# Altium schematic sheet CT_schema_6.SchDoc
size 406 x 311 mm
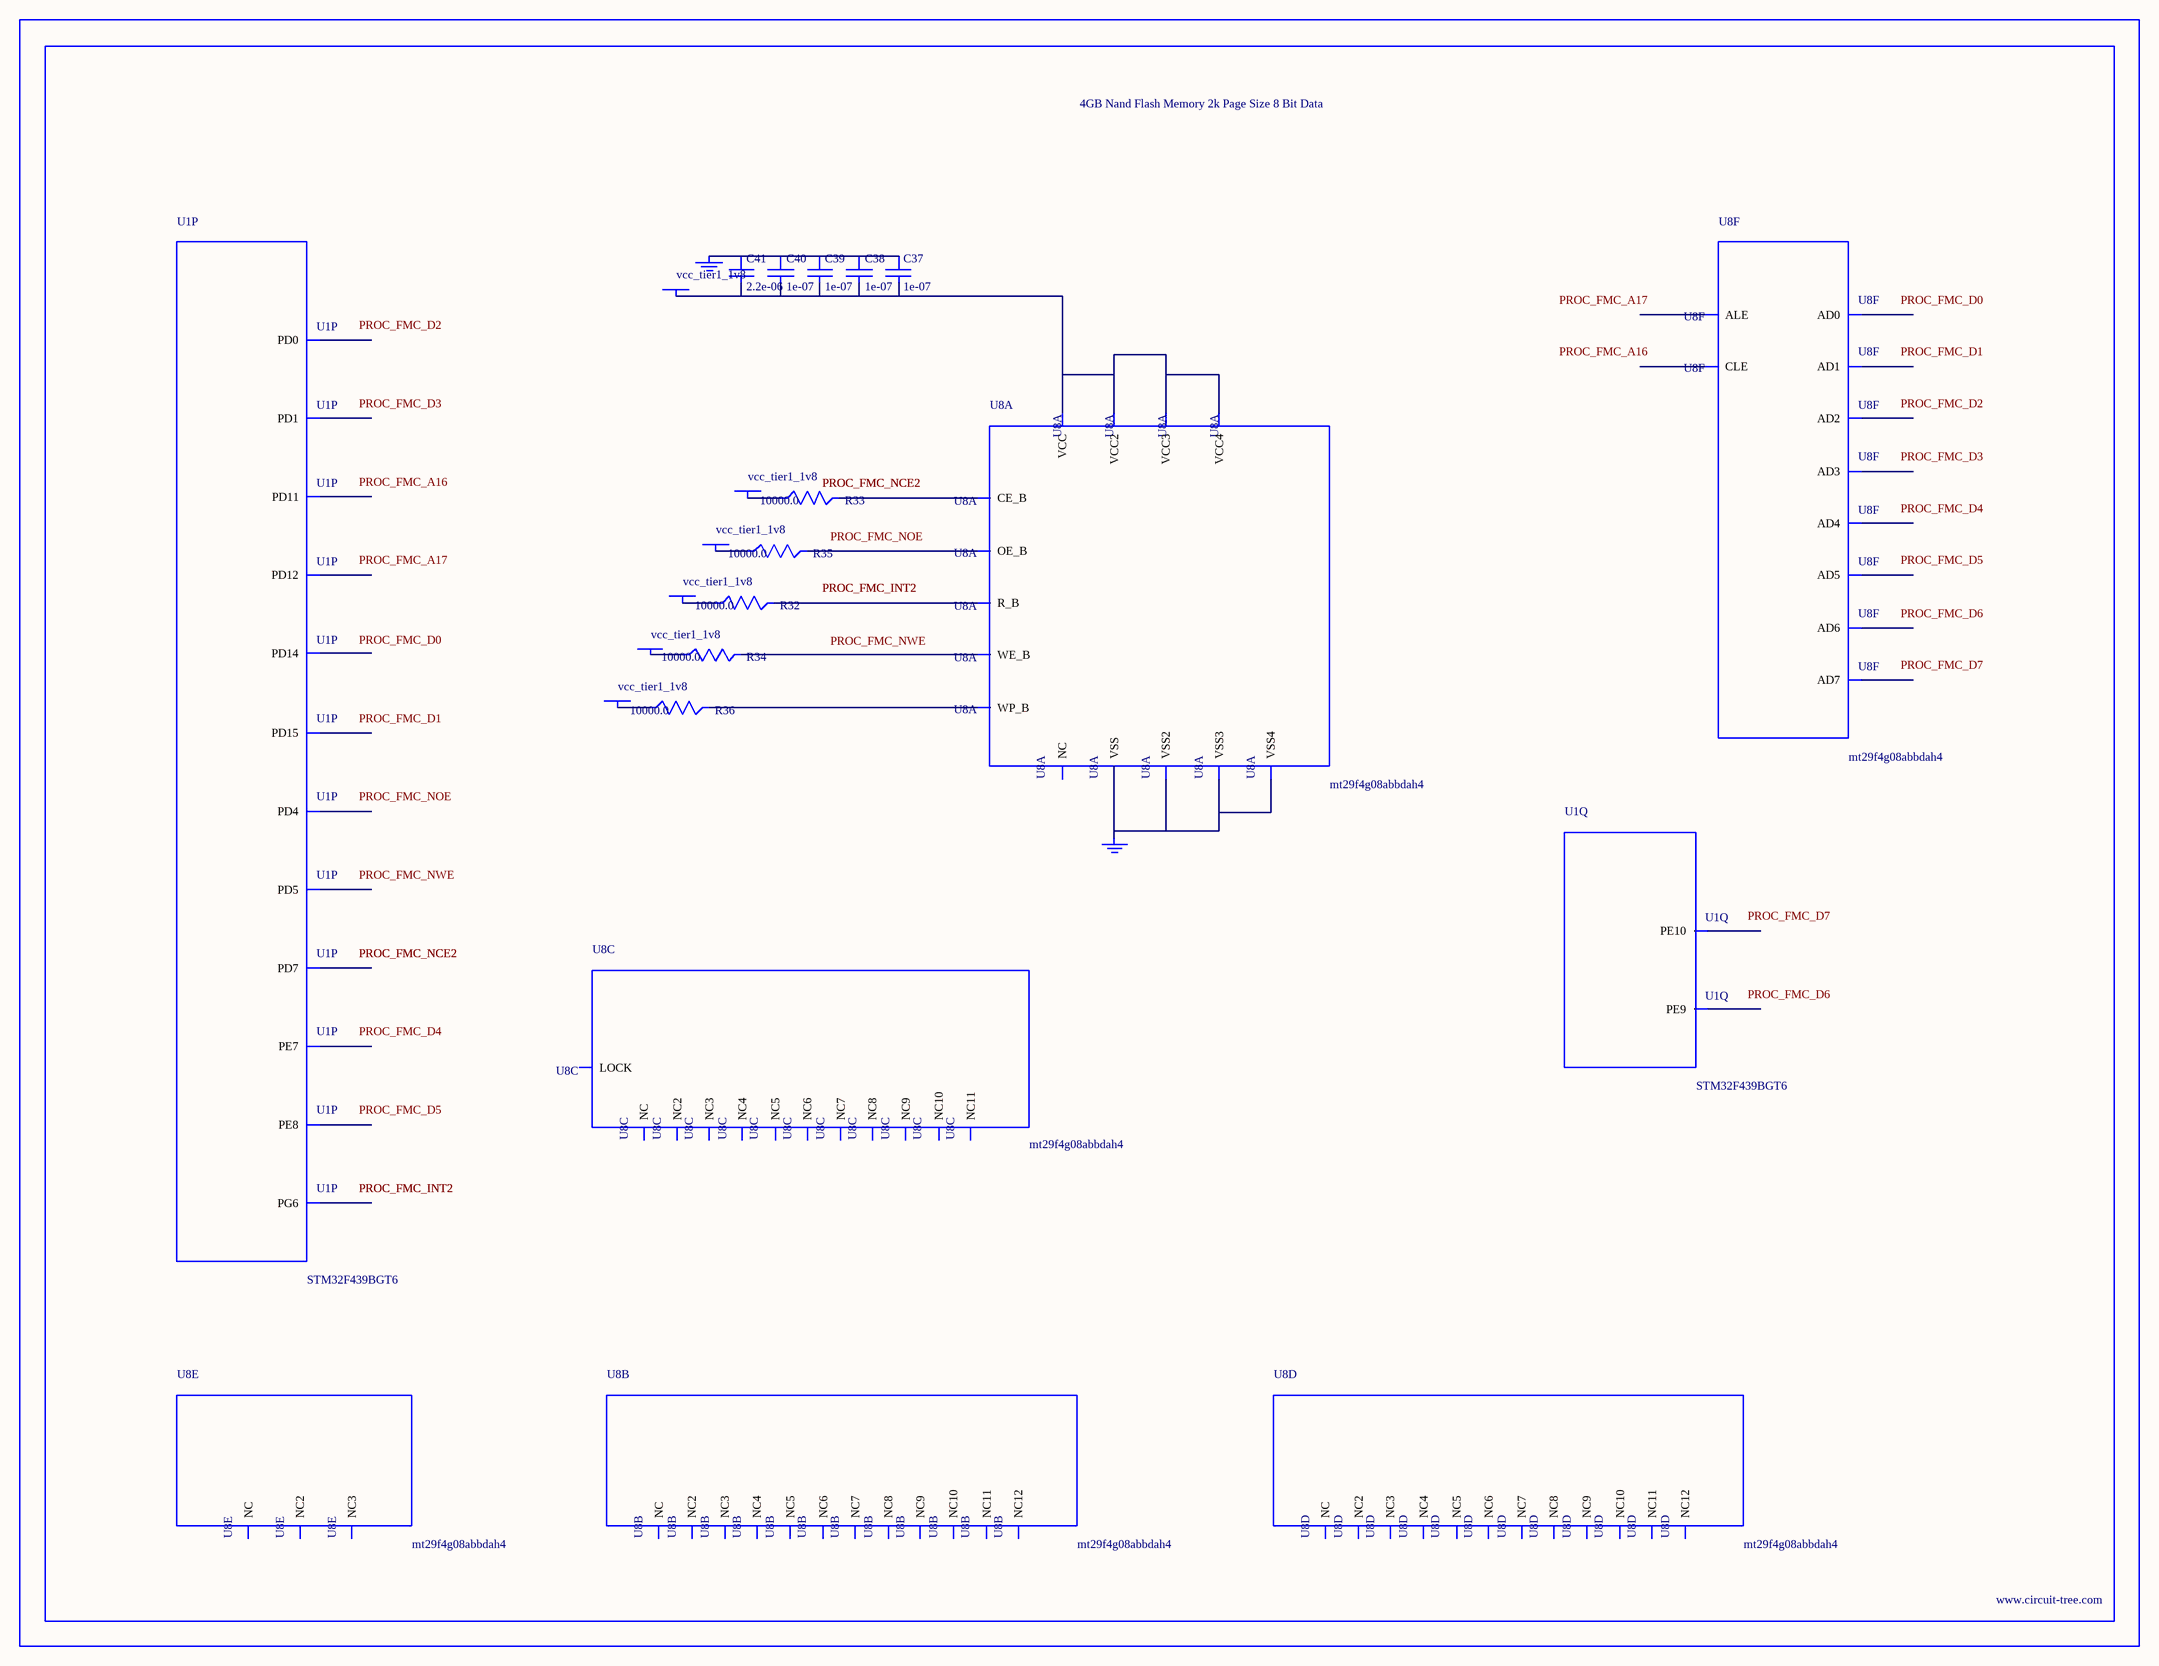
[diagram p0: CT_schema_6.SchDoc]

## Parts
BORDER5  (no value)
C37  1e-07  [C0402]
C38  1e-07  [C0402]
C39  1e-07  [C0402]
C40  1e-07  [C0402]
C41  2.2e-06  [C0603]
GND_INSTANCE_5_0  (no value)
GND_INSTANCE_5_1  (no value)
POWER_INSTANCE_5_0  vcc_tier1_1v8
POWER_INSTANCE_5_1  vcc_tier1_1v8
POWER_INSTANCE_5_2  vcc_tier1_1v8
POWER_INSTANCE_5_3  vcc_tier1_1v8
POWER_INSTANCE_5_4  vcc_tier1_1v8
POWER_INSTANCE_5_5  vcc_tier1_1v8
R32  10000.0  [R0603]
R33  10000.0  [R0603]
R34  10000.0  [R0603]
R35  10000.0  [R0603]
R36  10000.0  [R0603]
U1  STM32F439BGT6  [LQFP208]  (parts P,Q of 18)
U8  mt29f4g08abbdah4  [VFBGA-63]  (parts A,B,C,D,E,F of 6)

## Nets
NetC37_1: C37.1 C38.1 C39.1 C40.1 C41.1 GND_INSTANCE_5_0.0(GND)
NetC37_2: C37.2 C38.2 C39.2 C40.2 C41.2 POWER_INSTANCE_5_0.0(PWR) U8.D3(VCC) U8.G4(VCC2) U8.H8(VCC3) U8.J6(VCC4)
NetGND_INSTANCE_5_1_0: GND_INSTANCE_5_1.0(GND) U8.C5(VSS) U8.F7(VSS2) U8.K3(VSS3) U8.K8(VSS4)
NetPOWER_INSTANCE_5_1_0: POWER_INSTANCE_5_1.0(PWR) R32.1
NetPOWER_INSTANCE_5_2_0: POWER_INSTANCE_5_2.0(PWR) R33.1
NetPOWER_INSTANCE_5_3_0: POWER_INSTANCE_5_3.0(PWR) R34.1
NetPOWER_INSTANCE_5_4_0: POWER_INSTANCE_5_4.0(PWR) R35.1
NetPOWER_INSTANCE_5_5_0: POWER_INSTANCE_5_5.0(PWR) R36.1
NetR32_2: R32.2 U8.C8(R_B)
NetR33_2: R33.2 U8.C6(CE_B)
NetR34_2: R34.2 U8.C7(WE_B)
NetR35_2: R35.2 U8.D4(OE_B)
NetR36_2: R36.2 U8.C3(WP_B)

Not connected (* = marked no-connect by the designer): U1 79(PE7) 80(PE8) 81(PE9) 84(PE10) 111(PD11) 112(PD12) 116(PD14) 117(PD15) 133(PG6) 164(PD0) 165(PD1) 168(PD4) 169(PD5) 173(PD7); U8 A1(NC) A2(NC3) A9(NC4) A10(NC2) B1(NC5) B9(NC7) B10(NC6) C4(ALE) D5(CLE) D6(NC8) D7(NC9) D8(NC10) E3(NC11) E4(NC12) E5(NC) E6(NC2) E7(NC3) E8(NC4) F3(NC5) F4(NC6) F5(NC7) F6(NC8) F8(NC9) G3(NC) G5(LOCK) G6(NC10) G7(NC11) G8(NC) H3(NC2) H4(AD0) H5(NC3) H6(NC4) H7(NC5) J3(NC6) J4(AD1) J5(NC7) J7(AD5) J8(AD7) K4(AD2) K5(AD3) K6(AD4) K7(AD6) L1(NC8) L2(NC10) L9(NC11) L10(NC9) M1(NC12) M2(NC2) M9(NC3) M10(NC)

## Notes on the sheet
- Labels drawn without touching a wire or pin: PROC_FMC_A16, PROC_FMC_A17, PROC_FMC_D0, PROC_FMC_D1, PROC_FMC_D2, PROC_FMC_D3, PROC_FMC_D4, PROC_FMC_D5, PROC_FMC_D6, PROC_FMC_D7, PROC_FMC_NOE, PROC_FMC_NWE

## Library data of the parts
BORDER5 = BORDER_PAGE5
C37-C40 = C0402C104K3RACTU
C41 = C0603C225K8RACTU
GND_INSTANCE_5_0 GND_INSTANCE_5_1 = GND
POWER_INSTANCE_5_0-POWER_INSTANCE_5_5 = PWR
R32-R36 = RC0603JR-0710KL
